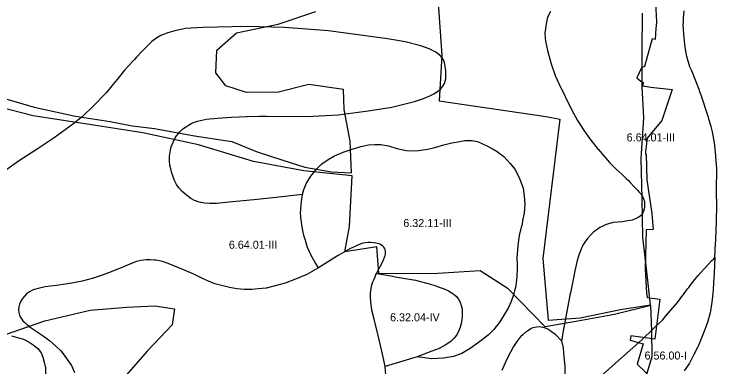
# Model space of a CAD drawing. Extents: x -555156 to -540209, y -1046851 to -1035695.
# Drawn here: x -543499 to -542625, y -1039885 to -1039446 of the extents above; entities that cross this region are included whole.
import ezdxf

# ---------------------------------------------------------------- set-up
doc = ezdxf.new("R2010")
doc.units = 0
for name, color, linetype in [('Vrstva 12', 7, 'Continuous'), ('Vrstva 27', 7, 'Continuous'), ('Vrstva 28', 7, 'Continuous'), ('Vrstva 29', 7, 'Continuous')]:
    doc.layers.add(name, color=color, linetype=linetype)

msp = doc.modelspace()

# ---------------------------------------------------------------- linework, layer by layer
at = {"layer": 'Vrstva 12'}
msp.add_lwpolyline([(-542701.38, -1039433.43), (-542700.2, -1039455.69), (-542700.61, -1039461.45), (-542700.78, -1039463.8), (-542701.79, -1039478.07), (-542705.63, -1039477.32), (-542715.23, -1039511.5), (-542718.9, -1039513.21), (-542724.537878, -1039525.815927), (-542719.79, -1039529.65), (-542716.77, -1039531.63), (-542717.09, -1039535.78), (-542707.08, -1039537.27), (-542680.77, -1039540.05), (-542693.55, -1039578.88), (-542711.82, -1039600.66), (-542713.86, -1039617.16), (-542713.67, -1039620.55), (-542712.89, -1039620.57), (-542712.36, -1039652.51), (-542705.86, -1039694.34), (-542704.55, -1039709.51), (-542704.14, -1039714.33), (-542712.81, -1039714.82), (-542714.22, -1039763.64), (-542712.47, -1039793.24), (-542711.823586, -1039798.848198), (-542695.88, -1039800.82), (-542702.05, -1039850.86), (-542732.14, -1039846.52), (-542733.07, -1039851.83), (-542716.86, -1039856.49), (-542724.18, -1039881.74), (-542694.14, -1039910.31)], dxfattribs=at)
at = {"layer": 'Vrstva 28'}
for points in [[(-542832.13, -1039443.36), (-542835.67, -1039450.43), (-542837.32, -1039458.45), (-542838.97, -1039470.01), (-542838.41, -1039475.84), (-542838.02, -1039479.92), (-542835.67, -1039491.48), (-542831.19, -1039508.47), (-542826, -1039522.62), (-542823.56, -1039528.16), (-542821.85, -1039532.04), (-542821.45, -1039532.87), (-542805.38, -1039566.04), (-542798.42, -1039578.63), (-542790.2, -1039591.49), (-542782.88, -1039601.65), (-542772.49, -1039614.68), (-542772.28, -1039614.95), (-542768.12, -1039619.7), (-542758.39, -1039630.79), (-542750.11, -1039639.1), (-542742.85, -1039646.11), (-542737.99, -1039650.8), (-542735.16, -1039653.59), (-542732.87, -1039655.84), (-542727.49, -1039661.48), (-542724.33, -1039664.87), (-542723.5, -1039665.77), (-542721.94, -1039667.45), (-542719.31, -1039670.58), (-542719.19, -1039670.77), (-542717.55, -1039673.36), (-542716.19, -1039676.19), (-542715.11, -1039679.51), (-542714.87, -1039682.92), (-542715.02, -1039686.1), (-542715.55, -1039689.02), (-542716.43, -1039691.8), (-542717.08, -1039693.44), (-542717.17, -1039693.6), (-542717.81, -1039694.81), (-542718.93, -1039696.32), (-542720.52, -1039697.86), (-542720.69, -1039698.03), (-542722.89, -1039699.49), (-542726.1, -1039701.2), (-542730.3, -1039702.52), (-542736.01, -1039703.64), (-542742.25, -1039704.67), (-542748.32, -1039705.1), (-542754.13, -1039705.79), (-542758.05, -1039706.72), (-542762.66, -1039708.18), (-542767.02, -1039710.06), (-542770.43, -1039711.93), (-542774.02, -1039714.33), (-542778.37, -1039717.74), (-542782.21, -1039721.5), (-542785.79, -1039725.68), (-542789.29, -1039730.21), (-542790.1, -1039731.47)], [(-542627.53, -1039749.28), (-542626.62, -1039731.47), (-542626.48, -1039728.66), (-542626.24, -1039724.02), (-542625.96, -1039718.42), (-542625.55, -1039701.61), (-542625.18, -1039686.78), (-542625.24, -1039682.75), (-542625.43, -1039669.9), (-542625.49, -1039665.46), (-542625.39, -1039660.54), (-542625.32, -1039657.08), (-542625.13, -1039647.13), (-542624.97, -1039638.78), (-542626.18, -1039623.43), (-542626.27, -1039622.31), (-542628.1, -1039606.61), (-542630.45, -1039593.01), (-542632.35, -1039586.21), (-542634.92, -1039577.04), (-542635.54, -1039574.82), (-542644.42, -1039547.36), (-542646.08, -1039542.93), (-542647.1, -1039540.2), (-542652.26, -1039526.44), (-542655.53, -1039518.95), (-542656.8, -1039516.04), (-542658.54, -1039512.05), (-542662.46, -1039498.98), (-542663.16, -1039495.08), (-542665.07, -1039484.33), (-542666.12, -1039471.51), (-542666.87, -1039459.43), (-542666.75, -1039456.24), (-542666.66, -1039453.76), (-542666.57, -1039451.51), (-542665.82, -1039442.54)], [(-543095.99, -1039571.6), (-543058.61, -1039566.63), (-543029.34, -1039562.18), (-543000.97, -1039555.17), (-542990.05, -1039551.5), (-542981.94, -1039548.09), (-542976.9, -1039545.52), (-542972.31, -1039542.48), (-542971.05, -1039541.64), (-542968.2, -1039539.25), (-542967.47, -1039538.26), (-542965.74, -1039535.94), (-542963.97, -1039532.78), (-542962.81, -1039529.78), (-542962.27, -1039526.85), (-542961.96, -1039523.46), (-542962.04, -1039519.99), (-542962.27, -1039516.6), (-542962.81, -1039511.52), (-542963.79, -1039506.47), (-542965.02, -1039503.39), (-542966.79, -1039500.62), (-542969.49, -1039497.69), (-542972.34, -1039495.23), (-542975.42, -1039493.3), (-542978.73, -1039491.61), (-542982.96, -1039489.68), (-542993.06, -1039485.96), (-543012.66, -1039480.73), (-543024.8, -1039478.71), (-543034.62, -1039477.07), (-543059.29, -1039474), (-543077.54, -1039471.44), (-543087.13, -1039470.09), (-543108.23, -1039467.13), (-543162.67, -1039463.01), (-543210.24, -1039461.64), (-543264.42, -1039463.28), (-543285.93, -1039464.48), (-543299.15, -1039467.16), (-543299.22, -1039467.17), (-543308.03, -1039469.71), (-543316.7, -1039473.15), (-543321.77, -1039475.99), (-543327.6, -1039480.62), (-543332.38, -1039484.95), (-543339.25, -1039492.13), (-543346.86, -1039500.13), (-543349.49, -1039502.9), (-543351.05, -1039504.53), (-543361.66, -1039516.34), (-543363.26, -1039518.28), (-543371.07, -1039527.7), (-543374.02, -1039531.24), (-543384.79, -1039544.15), (-543400.21, -1039560.37), (-543414.07, -1039573.97), (-543426.35, -1039583.91), (-543449.1, -1039600.38), (-543470.53, -1039614.24), (-543493.68, -1039629.17), (-543521.66, -1039649.33)], [(-543140.5, -1039670.81), (-543177.21, -1039674.91), (-543196.7, -1039677.08), (-543235.57, -1039680.93), (-543247.18, -1039681.96), (-543255.63, -1039682.04), (-543262.46, -1039681.61), (-543268.86, -1039680.25), (-543274.66, -1039678.2), (-543279.36, -1039675.64), (-543284.74, -1039671.7), (-543289.95, -1039667), (-543294.04, -1039662.56), (-543297.03, -1039658.2), (-543299.51, -1039653.59), (-543301.38, -1039648.98), (-543302.84, -1039644.45), (-543304.29, -1039638.99), (-543305.23, -1039634.46), (-543305.82, -1039629.25), (-543305.81, -1039628.82), (-543305.75, -1039625.11), (-543305.72, -1039623.24), (-543304.61, -1039615.72), (-543303.67, -1039611.45), (-543301.36, -1039605.65), (-543298.63, -1039600.26), (-543296.97, -1039597.8), (-543296.33, -1039596.85), (-543292.96, -1039592.9), (-543292.4, -1039592.24), (-543289.16, -1039589.25), (-543286, -1039586.86), (-543282.33, -1039584.38), (-543278.15, -1039582.16), (-543274.56, -1039580.71), (-543271.15, -1039579.6), (-543267.39, -1039578.57), (-543260.22, -1039577.26), (-543246.33, -1039575.77), (-543228.86, -1039574.72), (-543210.55, -1039573.86), (-543209.74, -1039573.82), (-543194.23, -1039573.41), (-543185.39, -1039573.17), (-543135.46, -1039573.69), (-543095.99, -1039571.6)], [(-543140.5, -1039670.81), (-543138.71, -1039664.78), (-543135.42, -1039656.85), (-543130.04, -1039647.89), (-543123.32, -1039639.67), (-543122.27, -1039638.64), (-543119.57, -1039636), (-543116.3, -1039632.79), (-543108.54, -1039627.11), (-543100.47, -1039622.78), (-543089.86, -1039618.3), (-543078.51, -1039614.56), (-543067.76, -1039611.12), (-543058.5, -1039609.03), (-543050.43, -1039608.43), (-543042.81, -1039608.73), (-543033.55, -1039610.23), (-543023.25, -1039613.51), (-543011.6, -1039616.05), (-543004.43, -1039616.5), (-542996.21, -1039616.05), (-542984.71, -1039614.41), (-542975.75, -1039612.32), (-542964.83, -1039609.17), (-542954.68, -1039606.63), (-542946.91, -1039605.14), (-542938.4, -1039603.79), (-542929.58, -1039603.64), (-542922.71, -1039604.99), (-542917.18, -1039607.38), (-542910.16, -1039610.52), (-542903.21, -1039614.52)], [(-542903.21, -1039614.52), (-542898.22, -1039617.39), (-542894.55, -1039620.06), (-542890, -1039623.37), (-542882.38, -1039631.74), (-542876.11, -1039639.66), (-542870.43, -1039650.87), (-542868.92, -1039654.94), (-542865.95, -1039662.97), (-542864.61, -1039672.54), (-542863.86, -1039683.15), (-542864.91, -1039694.21), (-542866.64, -1039703.31), (-542867.4, -1039707.33), (-542867.82, -1039709.53), (-542867.9, -1039709.83), (-542870.96, -1039721.82), (-542872.79, -1039734.11), (-542873.83, -1039749.8), (-542873.56, -1039757.07), (-542873.48, -1039759.14), (-542873.4, -1039761.31), (-542873.31, -1039763.66), (-542873.93, -1039771.99), (-542874.35, -1039777.53), (-542875.7, -1039786.39), (-542875.87, -1039787.54), (-542876.68, -1039790.74), (-542877.96, -1039795.76), (-542880.94, -1039803.68), (-542884.83, -1039812.05), (-542889.16, -1039819.82), (-542895.13, -1039829.09), (-542902.45, -1039838.65), (-542909.17, -1039845.53), (-542909.51, -1039845.8), (-542921.57, -1039855.09), (-542931.73, -1039862.41), (-542942.19, -1039868.42), (-542952.79, -1039872.45), (-542965.04, -1039874.55), (-542979.83, -1039875.29), (-542988.49, -1039874.1), (-542997.75, -1039872.9)], [(-543120.45, -1039762.18), (-543124.78, -1039755.31), (-543129.65, -1039746.51), (-543130.16, -1039745.59), (-543131.38, -1039742.83), (-543134.04, -1039736.77), (-543136.88, -1039728.15), (-543138.33, -1039723.11), (-543139.7, -1039717.56), (-543140.89, -1039711.32), (-543141.83, -1039705.35), (-543142.43, -1039699.88), (-543142.59, -1039697.23), (-543142.77, -1039694.42), (-543142.6, -1039688.86), (-543142.17, -1039683.23), (-543141.28, -1039676.59), (-543140.5, -1039670.81)], [(-543048.49, -1039769.02), (-543046.44, -1039765.43), (-543043.63, -1039760.22), (-543041.92, -1039756.55), (-543040.14, -1039753.01), (-543039.22, -1039751.05), (-543038.34, -1039748.86), (-543037.61, -1039746.47), (-543037.27, -1039744.91), (-543037.02, -1039743), (-543037.12, -1039741.15), (-543037.46, -1039739.39), (-543038.39, -1039737.73), (-543039.46, -1039736.27), (-543040.63, -1039735.05), (-543042.29, -1039733.68), (-543044.19, -1039732.61), (-543046.48, -1039731.88), (-543049.17, -1039731.19), (-543052.19, -1039730.71), (-543056.04, -1039730.46), (-543059.26, -1039730.51), (-543062.34, -1039730.8), (-543065.34, -1039731.38), (-543068.58, -1039732.4), (-543073.67, -1039734.71), (-543074.21, -1039734.96), (-543080.53, -1039738.04), (-543090.17, -1039743.25), (-543096.23, -1039746.75), (-543098.28, -1039747.94), (-543120.45, -1039762.18)], [(-542790.1, -1039731.47), (-542791.6, -1039733.8), (-542793.99, -1039738.66), (-542796.01, -1039743.79), (-542798.25, -1039751.11), (-542801.69, -1039765.76), (-542803.05, -1039772.42), (-542803.9, -1039776.63), (-542807.22, -1039792.94), (-542807.74, -1039795.48), (-542807.96, -1039796.54), (-542815.66, -1039838.18), (-542818.36, -1039852.76)], [(-543120.45, -1039762.18), (-543135.02, -1039770.38), (-543149.06, -1039776.21), (-543161.91, -1039781.14), (-543174.61, -1039784.58), (-543185.51, -1039787.12), (-543195.52, -1039788.32), (-543203.43, -1039788.77), (-543212.84, -1039788.77), (-543221.95, -1039788.02), (-543231.36, -1039786.38), (-543239.58, -1039784.58), (-543249.29, -1039781.74), (-543254.57, -1039779.65), (-543257.21, -1039778.6), (-543264.82, -1039775.17), (-543274.94, -1039770.49), (-543289.36, -1039764), (-543300.29, -1039759.47), (-543307.46, -1039756.57), (-543314.46, -1039754.18), (-543322.57, -1039752.55), (-543324.86, -1039752.41), (-543329.31, -1039752.13), (-543330.96, -1039752.15), (-543335.03, -1039752.21), (-543341.51, -1039752.9), (-543346.72, -1039754.26), (-543352.18, -1039756.14), (-543363.02, -1039760.62), (-543380.64, -1039767.64), (-543390.65, -1039771.68), (-543402.15, -1039775.41), (-543414.4, -1039778.4), (-543425.3, -1039780.65), (-543435.01, -1039782.14), (-543446.22, -1039783.93), (-543460.38, -1039785.45), (-543469.35, -1039787.67), (-543475.24, -1039789.55), (-543480.02, -1039791.77), (-543483.6, -1039794.33), (-543486.33, -1039797.23), (-543488.81, -1039800.31), (-543490.6, -1039803.38), (-543492.22, -1039807.31), (-543493.16, -1039810.64), (-543493.5, -1039814.06), (-543493.07, -1039817.73), (-543492.56, -1039820.8), (-543491.03, -1039823.79), (-543489.66, -1039826.01), (-543488.12, -1039827.98), (-543485.82, -1039830.2), (-543483.17, -1039832.42), (-543480.94, -1039834.31), (-543480.26, -1039834.89), (-543464.28, -1039845.95), (-543455.17, -1039852.53), (-543447.1, -1039859.4), (-543440.83, -1039865.08), (-543436.79, -1039870.61), (-543432.92, -1039875.89), (-543427.69, -1039883.66), (-543424.11, -1039892.03)], [(-542799.7, -1039922.92), (-542766.24, -1039893.88), (-542718.4, -1039851.52), (-542716.86, -1039850.04), (-542705.95, -1039839.57), (-542701.66, -1039835.46), (-542696.42, -1039830.43), (-542692.73, -1039826.9), (-542688.04, -1039821.34), (-542674.17, -1039804.93), (-542667.3, -1039795.89), (-542666.74, -1039795.15), (-542662.79, -1039789.96), (-542661.5, -1039788.26), (-542660.05, -1039786.36), (-542658.15, -1039783.99), (-542652.27, -1039776.67), (-542648.29, -1039771.72), (-542645.15, -1039767.8), (-542640.36, -1039762.76), (-542631.55, -1039753.5), (-542628.91, -1039750.73), (-542627.53, -1039749.28)], [(-542627.53, -1039749.28), (-542628.5, -1039768.34), (-542628.84, -1039774.91), (-542629.13, -1039780.17), (-542629.64, -1039789.41), (-542630.43, -1039797.49), (-542631.13, -1039804.65), (-542632.83, -1039815.46), (-542633.22, -1039817.95), (-542636.66, -1039830.21), (-542642.19, -1039844.26), (-542648, -1039858.46), (-542648.87, -1039860.24), (-542653.98, -1039870.71), (-542659.06, -1039880.42), (-542665.78, -1039889.99)], [(-543054.79, -1039784.73), (-543052.99, -1039779.5), (-543052.25, -1039777.84), (-543051.82, -1039776.88), (-543050.11, -1039773.03), (-543049.01, -1039770.3), (-543048.49, -1039769.02)], [(-543048.49, -1039769.02), (-543045.55, -1039769.52), (-543030.53, -1039772.11), (-543022.76, -1039773.44), (-543000.07, -1039777.33), (-542981.21, -1039782.15), (-542976.02, -1039783.93), (-542970.3, -1039785.89), (-542964.03, -1039788.28), (-542960.34, -1039789.98), (-542958.99, -1039790.6), (-542955.41, -1039792.57), (-542951.65, -1039795.04), (-542948.41, -1039797.95), (-542946.36, -1039800.94), (-542944.23, -1039804.78), (-542943.03, -1039808.79), (-542942.01, -1039813.23), (-542941.92, -1039817.85), (-542941.84, -1039822.03), (-542942.44, -1039826.81), (-542943.12, -1039831.08), (-542944.4, -1039835.78), (-542946.19, -1039840.05), (-542948.24, -1039844.41), (-542950.22, -1039847.54), (-542952.36, -1039850.11), (-542955.18, -1039853.01), (-542955.36, -1039853.15), (-542958.33, -1039855.4), (-542962.86, -1039858.3), (-542970.54, -1039862.49), (-542979.42, -1039865.82), (-542997.75, -1039872.9)], [(-543037.61, -1039884.89), (-543039.25, -1039876.97), (-543041.8, -1039865.62), (-543046.12, -1039846.34), (-543051.2, -1039825.98), (-543054.19, -1039814.48), (-543055.53, -1039804.16), (-543055.92, -1039797.9), (-543055.98, -1039796.99), (-543055.73, -1039793.45), (-543055.53, -1039790.56), (-543054.79, -1039784.73)], [(-542818.36, -1039852.76), (-542825.53, -1039845.31), (-542830.57, -1039841.55), (-542832.77, -1039840.1), (-542835.29, -1039838.44), (-542838.16, -1039837.03), (-542840.94, -1039836.15), (-542843.48, -1039835.71), (-542846.26, -1039835.56), (-542849.58, -1039835.76), (-542851.48, -1039836.15), (-542853.97, -1039836.74), (-542855.97, -1039837.66), (-542857.82, -1039838.74), (-542860.65, -1039840.64), (-542863.48, -1039842.59), (-542863.9, -1039842.96), (-542866.01, -1039844.84), (-542869.14, -1039847.86), (-542871.33, -1039850.4), (-542873.77, -1039853.72), (-542877.82, -1039859.72), (-542881.92, -1039866.81), (-542886.87, -1039876.63), (-542892.67, -1039889.87)], [(-543502.29, -1039846.72), (-543494.67, -1039848.51), (-543487.5, -1039850.9), (-543480.33, -1039854.49), (-543474.06, -1039858.52), (-543469.43, -1039862.41), (-543465.55, -1039867.79), (-543463.31, -1039873.02), (-543461.51, -1039879.45), (-543460.02, -1039886.32), (-543459.87, -1039892.6), (-543460.77, -1039900.37), (-543461.81, -1039906.5), (-543463.6, -1039912.33), (-543466.59, -1039918.45), (-543470.18, -1039923.68), (-543471.01, -1039924.74), (-543473.76, -1039928.23), (-543476.91, -1039931.19), (-543478.54, -1039932.72), (-543483.32, -1039936.3), (-543489.89, -1039940.34), (-543497.36, -1039944.08), (-543506.92, -1039947.36)], [(-542818.36, -1039852.76), (-542816.32, -1039861.42), (-542815.63, -1039868.34), (-542814.87, -1039876.62), (-542814.27, -1039884.31), (-542814.35, -1039893.44), (-542815.29, -1039904.12), (-542817.08, -1039917.86), (-542818.25, -1039926.9), (-542818.86, -1039931.59), (-542819.85, -1039936.07), (-542820.83, -1039939.15), (-542821.28, -1039940.46), (-542821.91, -1039942.27)], [(-542997.75, -1039872.9), (-543037.61, -1039884.89)], [(-543152.9, -1039997.36), (-543121.08, -1039983.16), (-543084, -1039964.67), (-543075.98, -1039959.89), (-543069.07, -1039955.2), (-543062.32, -1039950.24), (-543055.24, -1039944.26), (-543049.35, -1039938.63), (-543046.36, -1039935.47), (-543044.23, -1039932.82), (-543041.75, -1039928.98), (-543040.13, -1039925.9), (-543038.85, -1039922.83), (-543037.66, -1039918.82), (-543036.76, -1039912.99), (-543036.37, -1039908.06), (-543036.29, -1039901.57), (-543036.63, -1039895.08), (-543037.05, -1039890.13), (-543037.61, -1039884.89)]]:
    msp.add_lwpolyline(points, dxfattribs=at)
at = {"layer": 'Vrstva 29'}
for points in [[(-542971.692993, -1039432.945007), (-542967.20697, -1039497.880005), (-542970.575012, -1039554.151001), (-542837.427002, -1039573.892029), (-542820.437012, -1039576.956909), (-542841.520996, -1039750.401001), (-542834.97998, -1039826.952026), (-542794.947021, -1039824.200012), (-542744.820007, -1039813.815979), (-542707.528015, -1039808.036987), (-542712.320984, -1039766.559998), (-542716.963013, -1039723.822998), (-542717.887024, -1039675.648987), (-542719.135986, -1039625.903015), (-542715.943909, -1039575.40802), (-542718.036987, -1039537.065002), (-542718.148987, -1039492.823975), (-542717.588989, -1039445.08197)], [(-543516.460998, -1039549.549998), (-543473.994004, -1039562.324995), (-543422.674998, -1039573.405998), (-543379.601007, -1039579.864999), (-543352.271004, -1039585.312006), (-543324.471004, -1039588.510001), (-543274.779002, -1039597.903992), (-543228.413005, -1039604.682009), (-543196.953008, -1039617.667), (-543164.974, -1039627.898005), (-543137.479, -1039636.930007), (-543104.531007, -1039642.410003), (-543079.621994, -1039643.798996), (-543080.968992, -1039604.663001), (-543088.643995, -1039564.914003), (-543089.578998, -1039540.095004), (-543132.702001, -1039534.140002), (-543170.398996, -1039543.497007), (-543210.054002, -1039543.997009), (-543235.572995, -1039535.665001), (-543248.342006, -1039519.643991), (-543247.164002, -1039491.458998), (-543222.346992, -1039469.894005), (-543170.712008, -1039459.080998), (-543123.677993, -1039442.978006)], [(-542714.244019, -1039901.062012), (-542705.434998, -1039872.200989), (-542706.007019, -1039840.430908), (-542707.112976, -1039808.853027), (-542752.473999, -1039820.062012), (-542797.97998, -1039828.184998), (-542838.510986, -1039835.367004), (-542884.804016, -1039788.23291), (-542919.36499, -1039765.606018), (-542972.067993, -1039768.922974), (-543023.997986, -1039769.510986), (-543045.411011, -1039768.96991), (-543048.124023, -1039736.075012), (-543087.78302, -1039741.927979), (-543081.960999, -1039710.622986), (-543078.468018, -1039647.734985), (-543138.674988, -1039641.403015), (-543201.434998, -1039629.726013), (-543269.951904, -1039608.823975), (-543338.822021, -1039594.260986), (-543402.741028, -1039584.000977), (-543475.52002, -1039572.88501), (-543546.606995, -1039554.794006)], [(-543519.895996, -1039848.265991), (-543460.958984, -1039827.960999), (-543404.499023, -1039814.809021), (-543358.88501, -1039810.807007), (-543324.244019, -1039809.312988), (-543299.807007, -1039812.950012), (-543302.510986, -1039833.083984), (-543333.484009, -1039865.526001), (-543379.687988, -1039918.166016), (-543422.891907, -1039974.155029), (-543461.947998, -1040029.524902), (-543501.424011, -1040081.284973)]]:
    msp.add_lwpolyline(points, dxfattribs=at)

# ---------------------------------------------------------------- texts
at = {"layer": 'Vrstva 27'}
for s, p in [('6.64.01-III', (-542737.246548, -1039604.76)), ('6.32.11-III', (-543015.036548, -1039711.29)), ('6.64.01-III', (-543232.026548, -1039738.28)), ('6.32.04-IV', (-543031.487119, -1039828.52)), ('6.56.00-I', (-542715.053906, -1039876.09))]:
    msp.add_text(s, height=10, dxfattribs=at).set_placement(p)

doc.saveas('drawing.dxf')
